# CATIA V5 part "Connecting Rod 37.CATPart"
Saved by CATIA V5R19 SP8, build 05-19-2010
Part number: Connecting Rod 37
Bounding box of the stored display mesh (mm): x -17.5 to 17.5, y 573.037 to 687.653, z 492.278 to 611.998
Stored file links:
  G:\EU_thinkMotion\CFAO_2010\MMS_groupe3\MMS_groupe3\A reprendre\fovide\fovide\Connecting Rod 37.CATPart
  G:\EU_thinkMotion\CFAO_2010\MMS_groupe3\MMS_groupe3\A reprendre\fovide\fovide\fovide.CATProduct
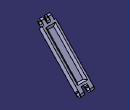
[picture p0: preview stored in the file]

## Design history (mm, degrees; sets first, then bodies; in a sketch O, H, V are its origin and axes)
Set1
  Plane1: linked copy from another document
  Line1 to Line3: linked copy from another document
  Plane2: linked copy from another document
  Plane3: linked copy from another document
Body1 (main body)
  Sketch1 on Plane1, origin (0, 606.2782, 577.4078), H (1, 0, 0), V (0, -0.6897, 0.7241)
    line L1 (-17.5, 30.1034) -> (-17.5, -114.8966)
    line L2 (-17.5, -114.8966) -> (-7.5, -114.8966)
    line L3 (-7.5, -114.8966) -> (-7.5, -98.8966)
    line L4 (-7.5, -98.8966) -> (7.5, -98.8966)
    line L5 (7.5, -98.8966) -> (7.5, -114.8966)
    point P6 (7.5, -114.8966)
    line L6 (7.5, -114.8966) -> (17.5, -114.8966)
    line L7 (17.5, -114.8966) -> (17.5, 30.1034)
    line L8 (17.5, 30.1034) -> (13, 30.1034)
    line L9 (13, 30.1034) -> (13, 45.1034)
    line L10 (13, 45.1034) -> (5, 45.1034)
    line L11 (5, 45.1034) -> (5, 30.1034)
    point P12 (5, 30.1034)
    line L12 (5, 30.1034) -> (-5, 30.1034)
    line L13 (-5, 30.1034) -> (-5, 45.1034)
    point P14 (-5, 45.1034)
    line L14 (-5, 45.1034) -> (-13, 45.1034)
    line L15 (-13, 45.1034) -> (-13, 30.1034)
    point P16 (-13, 30.1034)
    line L16 (-17.5, 30.1034) -> (-13, 30.1034)
    reference projected line E1 (-150, -106.8966) -> (150, -106.8966) from Line1
    reference projected line E2 (0, -106.8966) -> (0, 38.1034) from Line2
    reference projected line E3 (0, -106.8966) -> (0, 38.1034) from Line2
    reference projected line E4 (-150, 38.1034) -> (150, 38.1034) from Line3
    length L5 = 16
    distance L6 E1 = 8
    length L4 = 15
    length L6 = 10
    length L2 = 10
    distance L5 E2 = 7.5
    length L9 = 15
    length L12 = 10
    distance L11 E3 = 5
    length L10 = 8
    length L14 = 8
    distance L10 E4 = 7
    vertical: L1 V, L3 V, L5 V, L7 V, L9 V, L11 V, L13 V, L15 V
    horizontal: L2 H, L4 H, L6 H, L8 H, L10 H, L12 H, L14 H, L16 H
    coincidence: P6 L2, P12 L8, P14 L10, P16 L8
  Pad1: profile Sketch1, direction (0, -0.7241, -0.6897), length 6, mirrored extent
  Fillet1: radius 5, on edge [start face of Pad1 | face of Pad1 from Sketch1.L6]; edge [face of Pad1 from Sketch1.L6 | end face of Pad1]; edge [start face of Pad1 | face of Pad1 from Sketch1.L2]; edge [face of Pad1 from Sketch1.L2 | end face of Pad1]; edge [start face of Pad1 | face of Pad1 from Sketch1.L10]; edge [start face of Pad1 | face of Pad1 from Sketch1.L14]; edge [face of Pad1 from Sketch1.L10 | end face of Pad1]; edge [face of Pad1 from Sketch1.L14 | end face of Pad1]
  Sketch2 on Plane2, origin (0, 607.7265, 578.7872), H (1, 0, 0), V (0, -0.6897, 0.7241)
    line L1 (-7.5, 20.1034) -> (7.5, 20.1034)
    line L2 (7.5, 20.1034) -> (7.5, -88.8966)
    line L3 (7.5, -88.8966) -> (-7.5, -88.8966)
    line L4 (-7.5, -88.8966) -> (-7.5, 20.1034)
    reference projected line E1 (5, 30.1034) -> (-5, 30.1034) from edge [face of Pad1 from Sketch1.L12 | end face of Pad1]
    reference projected line E2 (-7.5, -98.8966) -> (7.5, -98.8966) from edge [face of Pad1 from Sketch1.L4 | end face of Pad1]
    reference projected line E3 (12.5, 25.1034) -> (12.5, -93.8966) from Sketch3.L4
    reference projected line E4 (-12.5, -93.8966) -> (-12.5, 25.1034) from Sketch3.L2
    distance L1 E1 = 10
    distance L3 E2 = 10
    distance L2 E3 = 5
    distance L4 E4 = 5
    horizontal: L1 H, L3 H
    vertical: L2 V, L4 V
  Sketch3 on start face of Pad1, origin (0, 610.6231, 581.5458), H (-1, 0, 0), V (0, -0.6897, 0.7241)
    line L1 (-12.5, 25.1034) -> (12.5, 25.1034)
    line L2 (12.5, 25.1034) -> (12.5, -93.8966)
    line L3 (12.5, -93.8966) -> (-12.5, -93.8966)
    line L4 (-12.5, -93.8966) -> (-12.5, 25.1034)
    reference projected line E1 (-5, 30.1034) -> (5, 30.1034) from edge [start face of Pad1 | face of Pad1 from Sketch1.L12]
    reference projected line E2 (7.5, -98.8966) -> (-7.5, -98.8966) from edge [start face of Pad1 | face of Pad1 from Sketch1.L4]
    reference projected line E3 (17.5, 30.1034) -> (17.5, -114.8966) from edge [start face of Pad1 | face of Pad1 from Sketch1.L1]
    reference projected line E4 (-17.5, -114.8966) -> (-17.5, 30.1034) from edge [start face of Pad1 | face of Pad1 from Sketch1.L7]
    distance L1 E1 = 5
    distance L3 E2 = 5
    distance L2 E3 = 5
    distance L4 E4 = 5
    horizontal: L1 H, L3 H
    vertical: L2 V, L4 V
  Loft1: solid, Sections (Sketch2; Sketch3)
  Sketch4 on Plane3, origin (0, 604.83, 576.0285), H (1, 0, 0), V (0, -0.6897, 0.7241)
    line L1 (-7.5, 20.1034) -> (7.5, 20.1034)
    line L2 (7.5, 20.1034) -> (7.5, -88.8966)
    line L3 (7.5, -88.8966) -> (-7.5, -88.8966)
    line L4 (-7.5, -88.8966) -> (-7.5, 20.1034)
    reference projected line E1 (5, 30.1034) -> (-5, 30.1034) from edge [face of Pad1 from Sketch1.L12 | end face of Pad1]
    reference projected line E2 (-7.5, -98.8966) -> (7.5, -98.8966) from edge [face of Pad1 from Sketch1.L4 | end face of Pad1]
    reference projected line E3 (12.5, -93.8966) -> (12.5, 25.1034) from Sketch5.L2
    reference projected line E4 (-12.5, 25.1034) -> (-12.5, -93.8966) from Sketch5.L4
    distance L1 E1 = 10
    distance L3 E2 = 10
    distance L2 E3 = 5
    distance L4 E4 = 5
    horizontal: L1 H, L3 H
    vertical: L2 V, L4 V
  Sketch5 on end face of Pad1, origin (0, 601.9334, 573.2699), H (1, 0, 0), V (0, -0.6897, 0.7241)
    line L1 (-12.5, 25.1034) -> (12.5, 25.1034)
    line L2 (12.5, 25.1034) -> (12.5, -93.8966)
    line L3 (12.5, -93.8966) -> (-12.5, -93.8966)
    line L4 (-12.5, -93.8966) -> (-12.5, 25.1034)
    reference projected line E1 (5, 30.1034) -> (-5, 30.1034) from edge [face of Pad1 from Sketch1.L12 | end face of Pad1]
    reference projected line E2 (-7.5, -98.8966) -> (7.5, -98.8966) from edge [face of Pad1 from Sketch1.L4 | end face of Pad1]
    reference projected line E3 (17.5, -114.8966) -> (17.5, 30.1034) from edge [face of Pad1 from Sketch1.L7 | end face of Pad1]
    reference projected line E4 (-17.5, 30.1034) -> (-17.5, -114.8966) from edge [face of Pad1 from Sketch1.L1 | end face of Pad1]
    distance L1 E1 = 5
    distance L3 E2 = 5
    distance L2 E3 = 5
    distance L4 E4 = 5
    horizontal: L1 H, L3 H
    vertical: L2 V, L4 V
  Loft2: solid, Sections (Sketch4; Sketch5)
  Sketch6 on face of Pad1 from Sketch1.L15, origin (-13, 580, 605), H (0, 1, 0), V (0, 0, -1)
    point P1 (0, 0)
    intersected point E1 (0, 0) from Line3
    coincidence: E1 P1
  Hole1: placed by Sketch6, at (-13, 580, 605) direction (1, 0, 0), diameter 10, through (limit type 3)
  Sketch7 on face of Pad1 from Sketch1.L1, origin (-17.5, 680, 500), H (0, 1, 0), V (0, 0, -1)
    point P1 (0, 0)
    intersected point E1 (0, 0) from Line1
    coincidence: E1 P1
  Hole2: placed by Sketch7, at (-17.5, 680, 500) direction (1, 0, 0), diameter 10, through (limit type 3)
